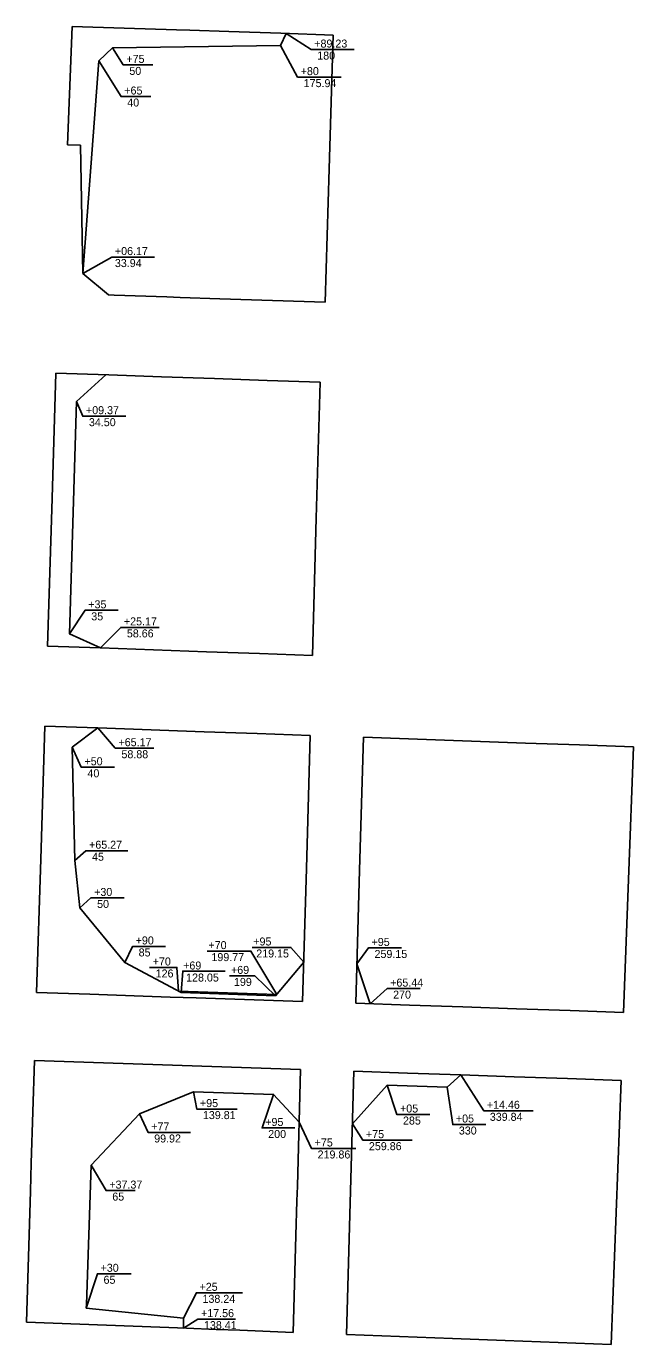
# Model space of a CAD drawing. Extents: x 979729 to 993523, y 1834148 to 1845433.
# Drawn here: x 992510 to 992966, y 1843154 to 1844143 of the extents above; entities that cross this region are included whole.
import ezdxf

# ---------------------------------------------------------------- set-up
doc = ezdxf.new("R2010")
doc.units = 0
for name, color, linetype in [('51', 7, 'Continuous'), ('53', 7, 'Continuous'), ('R_Draft', 7, 'Continuous'), ('S_EXIST_ROW', 7, 'Continuous')]:
    doc.layers.add(name, color=color, linetype=linetype)

msp = doc.modelspace()

# ---------------------------------------------------------------- linework, layer by layer
at = {"layer": '51'}
for p, q in [((992700.72, 1844128.38), (992705.03, 1844137.49)), ((992564.43, 1844117.07), (992574.7, 1844126.79)), ((992574.7, 1844126.79), (992700.72, 1844128.38)), ((992552.28, 1843957.59), (992564.43, 1844117.07)), ((992718.07, 1843441.15), (992697.04, 1843415.86)), ((992635.35, 1843343.93), (992594.87, 1843327.3)), ((992594.87, 1843327.3), (992558.61, 1843288.89)), ((992558.61, 1843288.89), (992555.03, 1843184.46)), ((992555.03, 1843184.46), (992554.93, 1843181.59))]:
    msp.add_line(p, q, dxfattribs=at)
for points in [[(992626.13, 1843418.29), (992583.83, 1843440.75), (992550.22, 1843481.93), (992546.43, 1843517.35), (992544.34, 1843602.2), (992563.73, 1843616.71)], [(992767.88, 1843409.86), (992758.05, 1843439.78)], [(992697.04, 1843415.86), (992626.13, 1843418.29)], [(992835.93, 1843356.52), (992825.77, 1843347.4), (992780.8, 1843348.95), (992754.65, 1843319.82)], [(992714.67, 1843321.2), (992695.51, 1843341.86), (992635.35, 1843343.93)], [(992554.93, 1843181.59), (992627.96, 1843174.08), (992627.87, 1843166.64)]]:
    msp.add_lwpolyline(points, dxfattribs=at)
at = {"layer": '53'}
msp.add_lwpolyline([(992697.85, 1843416.83), (992624.12, 1843419.36)], dxfattribs=at)
at = {"layer": 'R_Draft'}
for p, q in [((992729.64, 1844125.42), (992755.84, 1844125.42)), ((992588.67, 1844113.92), (992604.86, 1844113.92)), ((992719.45, 1844104.76), (992746.14, 1844104.76)), ((992587.11, 1844090.21), (992603.29, 1844090.21)), ((992580.04, 1843969.83), (992606.25, 1843969.83)), ((992558.34, 1843850.51), (992584.54, 1843850.51)), ((992560.08, 1843704.92), (992578.88, 1843704.92)), ((992586.8, 1843692.13), (992609.71, 1843692.13)), ((992582.74, 1843601.52), (992605.64, 1843601.52)), ((992557.23, 1843587.22), (992576.03, 1843587.22)), ((992560.68, 1843524.65), (992586.14, 1843524.65)), ((992564.47, 1843489.23), (992583.27, 1843489.23)), ((992595.64, 1843452.89), (992614.44, 1843452.89)), ((992645.67, 1843449.38), (992672.47, 1843449.38)), ((992679.35, 1843452.1), (992702.42, 1843452.1)), ((992772.6, 1843451.74), (992791.4, 1843451.74)), ((992616.98, 1843437.11), (992602.49, 1843437.11)), ((992633.28, 1843434.37), (992659.12, 1843434.37)), ((992662.38, 1843430.85), (992675.29, 1843430.85)), ((992786.57, 1843421.25), (992805.37, 1843421.25)), ((992643.86, 1843330.91), (992668.05, 1843330.91)), ((992793.95, 1843326.84), (992812.75, 1843326.84)), ((992859.09, 1843329.61), (992890.1, 1843329.61)), ((992692.85, 1843316.75), (992711.33, 1843316.75)), ((992835.85, 1843319.34), (992854.65, 1843319.34)), ((992607.3, 1843313.38), (992633.07, 1843313.38)), ((992768.39, 1843307.61), (992799.46, 1843307.61)), ((992729.91, 1843301.38), (992757.17, 1843301.38)), ((992575.87, 1843269.8), (992591.54, 1843269.8)), ((992569.3, 1843207.41), (992588.76, 1843207.41)), ((992643.53, 1843193.13), (992672.21, 1843193.13)), ((992644.66, 1843173.4), (992666.99, 1843173.4))]:
    msp.add_line(p, q, dxfattribs=at)
for points in [[(992705.03, 1844137.49), (992723.64, 1844125.42), (992729.64, 1844125.42)], [(992574.7, 1844126.79), (992582.67, 1844113.92), (992588.67, 1844113.92)], [(992700.72, 1844128.38), (992713.45, 1844104.76), (992719.45, 1844104.76)], [(992564.43, 1844117.07), (992581.11, 1844090.21), (992587.11, 1844090.21)], [(992552.28, 1843957.59), (992574.04, 1843969.83), (992580.04, 1843969.83)], [(992547.73, 1843861.61), (992552.34, 1843850.51), (992558.34, 1843850.51)], [(992542.25, 1843687.32), (992554.08, 1843704.92), (992560.08, 1843704.92)], [(992565.57, 1843676.69), (992580.8, 1843692.13), (992586.8, 1843692.13)], [(992563.73, 1843616.71), (992576.74, 1843601.52), (992582.74, 1843601.52)], [(992544.34, 1843602.2), (992551.23, 1843587.22), (992557.23, 1843587.22)], [(992546.43, 1843517.35), (992554.68, 1843524.65), (992560.68, 1843524.65)], [(992550.22, 1843481.93), (992558.47, 1843489.23), (992564.47, 1843489.23)], [(992583.83, 1843440.75), (992589.64, 1843452.89), (992595.64, 1843452.89)], [(992697.85, 1843416.83), (992678.47, 1843449.38), (992672.47, 1843449.38)], [(992718.07, 1843441.15), (992708.42, 1843452.1), (992702.42, 1843452.1)], [(992758.05, 1843439.78), (992766.6, 1843451.74), (992772.6, 1843451.74)], [(992624.12, 1843419.36), (992622.98, 1843437.11), (992616.98, 1843437.11)], [(992626.13, 1843418.29), (992627.28, 1843434.37), (992633.28, 1843434.37)], [(992697.04, 1843415.86), (992681.29, 1843430.85), (992675.29, 1843430.85)], [(992767.88, 1843409.86), (992780.57, 1843421.25), (992786.57, 1843421.25)], [(992835.93, 1843356.52), (992853.09, 1843329.61), (992859.09, 1843329.61)], [(992780.8, 1843348.95), (992787.95, 1843326.84), (992793.95, 1843326.84)], [(992825.77, 1843347.4), (992829.85, 1843319.34), (992835.85, 1843319.34)], [(992635.35, 1843343.93), (992637.86, 1843330.91), (992643.86, 1843330.91)], [(992695.51, 1843341.86), (992686.85, 1843316.75), (992692.85, 1843316.75)], [(992594.87, 1843327.3), (992601.3, 1843313.38), (992607.3, 1843313.38)], [(992714.67, 1843321.2), (992723.91, 1843301.38), (992729.91, 1843301.38)], [(992754.65, 1843319.82), (992762.39, 1843307.61), (992768.39, 1843307.61)], [(992558.61, 1843288.89), (992569.87, 1843269.8), (992575.87, 1843269.8)], [(992554.93, 1843181.59), (992563.3, 1843207.41), (992569.3, 1843207.41)], [(992627.96, 1843174.08), (992637.53, 1843193.13), (992643.53, 1843193.13)], [(992627.87, 1843166.64), (992638.66, 1843173.4), (992644.66, 1843173.4)]]:
    msp.add_lwpolyline(points, dxfattribs=at)
at = {"layer": 'S_EXIST_ROW'}
for p, q in [((992540.75, 1844054.04), (992544.3, 1844142.82)), ((992544.3, 1844142.82), (992583.48, 1844141.52)), ((992583.48, 1844141.52), (992622.66, 1844140.22)), ((992622.66, 1844140.22), (992632.65, 1844139.89)), ((992632.65, 1844139.89), (992661.84, 1844138.92)), ((992661.84, 1844138.92), (992701.02, 1844137.62)), ((992701.02, 1844137.62), (992740.19, 1844136.33)), ((992740.19, 1844136.33), (992737.2, 1844036.11)), ((992737.2, 1844036.11), (992734.2, 1843935.9)), ((992575.87, 1843941.3), (992571.74, 1843941.44)), ((992615.45, 1843939.95), (992575.87, 1843941.3)), ((992625.44, 1843939.61), (992615.45, 1843939.95)), ((992655.03, 1843938.6), (992625.44, 1843939.61)), ((992694.6, 1843937.25), (992655.03, 1843938.6)), ((992734.2, 1843935.9), (992694.6, 1843937.25)), ((992532.2, 1843882.76), (992529.01, 1843780.42)), ((992571.84, 1843881.41), (992532.2, 1843882.76)), ((992611.48, 1843880.05), (992571.84, 1843881.41)), ((992651.12, 1843878.7), (992611.48, 1843880.05)), ((992690.76, 1843877.35), (992651.12, 1843878.7)), ((992730.4, 1843875.99), (992690.76, 1843877.35)), ((992727.51, 1843773.99), (992730.4, 1843875.99)), ((992529.01, 1843780.73), (992525.81, 1843678.09)), ((992724.59, 1843671.08), (992727.51, 1843773.99)), ((992525.81, 1843678.09), (992565.57, 1843676.69)), ((992565.57, 1843676.69), (992605.32, 1843675.29)), ((992605.32, 1843675.29), (992645.08, 1843673.89)), ((992645.08, 1843673.89), (992684.83, 1843672.49)), ((992684.83, 1843672.49), (992724.59, 1843671.08)), ((992520.83, 1843518.23), (992523.94, 1843618.12)), ((992523.94, 1843618.12), (992563.73, 1843616.71)), ((992563.73, 1843616.71), (992603.52, 1843615.31)), ((992603.52, 1843615.31), (992623.42, 1843614.61)), ((992643.31, 1843613.91), (992623.42, 1843614.61)), ((992683.1, 1843612.51), (992643.31, 1843613.91)), ((992722.89, 1843611.11), (992683.1, 1843612.51)), ((992720.06, 1843511.34), (992722.89, 1843611.11)), ((992760.04, 1843509.96), (992762.87, 1843609.7)), ((992762.87, 1843609.7), (992803.41, 1843608.27)), ((992803.41, 1843608.27), (992843.96, 1843606.84)), ((992843.96, 1843606.84), (992884.51, 1843605.41)), ((992884.51, 1843605.41), (992925.06, 1843603.99)), ((992925.06, 1843603.99), (992965.6, 1843602.56)), ((992965.6, 1843602.56), (992961.85, 1843502.98)), ((992517.71, 1843418.35), (992520.83, 1843518.23)), ((992717.23, 1843411.58), (992720.06, 1843511.34)), ((992757.21, 1843410.22), (992760.04, 1843509.96)), ((992961.85, 1843502.98), (992958.1, 1843403.41)), ((992557.62, 1843417), (992517.71, 1843418.35)), ((992597.52, 1843415.64), (992557.62, 1843417)), ((992617.86, 1843414.95), (992597.52, 1843415.64)), ((992617.86, 1843414.95), (992637.43, 1843414.29)), ((992637.43, 1843414.29), (992717.23, 1843411.58)), ((992797.39, 1843408.86), (992757.21, 1843410.22)), ((992837.57, 1843407.5), (992797.39, 1843408.86)), ((992877.74, 1843406.13), (992837.57, 1843407.5)), ((992917.92, 1843404.77), (992877.74, 1843406.13)), ((992958.1, 1843403.41), (992917.92, 1843404.77)), ((992516.12, 1843367.38), (992513.72, 1843290.41)), ((992516.12, 1843367.38), (992715.79, 1843360.6)), ((992713.31, 1843273.04), (992715.79, 1843360.6)), ((992755.77, 1843359.24), (992752.97, 1843260.59)), ((992795.85, 1843357.88), (992755.77, 1843359.24)), ((992835.93, 1843356.52), (992795.85, 1843357.88)), ((992876.01, 1843355.16), (992835.93, 1843356.52)), ((992916.09, 1843353.8), (992876.01, 1843355.16)), ((992956.18, 1843352.44), (992916.09, 1843353.8)), ((992952.44, 1843253.36), (992956.18, 1843352.44)), ((992513.06, 1843269.28), (992513.72, 1843290.41)), ((992510, 1843171.18), (992513.06, 1843269.28)), ((992713, 1843262.04), (992713.31, 1843273.04)), ((992712.26, 1843236.01), (992713, 1843262.04)), ((992752.97, 1843260.59), (992750.17, 1843161.93)), ((992948.71, 1843154.28), (992952.44, 1843253.36)), ((992710.2, 1843163.47), (992712.26, 1843236.01)), ((992510, 1843171.18), (992550.04, 1843169.64)), ((992550.04, 1843169.64), (992590.08, 1843168.1)), ((992590.08, 1843168.1), (992630.12, 1843166.55)), ((992630.12, 1843166.55), (992652.37, 1843165.7)), ((992670.16, 1843165.01), (992652.37, 1843165.7)), ((992710.2, 1843163.47), (992670.16, 1843165.01)), ((992750.17, 1843161.93), (992789.88, 1843160.4)), ((992789.88, 1843160.4), (992829.59, 1843158.87)), ((992829.59, 1843158.87), (992849.44, 1843158.11)), ((992849.44, 1843158.11), (992869.29, 1843157.34)), ((992869.29, 1843157.34), (992909, 1843155.81)), ((992909, 1843155.81), (992948.71, 1843154.28))]:
    msp.add_line(p, q, dxfattribs=at)
for points in [[(992571.74, 1843941.44), (992552.28, 1843957.59), (992550.53, 1844053.71), (992540.75, 1844054.04)], [(992547.73, 1843861.61), (992569.7, 1843881.48)], [(992565.57, 1843676.69), (992542.25, 1843687.32), (992547.73, 1843861.61)]]:
    msp.add_lwpolyline(points, dxfattribs=at)

# ---------------------------------------------------------------- texts
at = {"layer": 'R_Draft'}
for s, p in [('+89.23', (992726.01, 1844126.92)), ('+75', (992585.05, 1844115.42)), (' 180', (992726.01, 1844117.92)), (' 50', (992585.05, 1844106.42)), ('+80', (992715.82, 1844106.26)), ('+65', (992583.48, 1844091.71)), (' 175.94', (992715.82, 1844097.26)), (' 40', (992583.48, 1844082.71)), ('33.94', (992576.42, 1843962.33)), ('+06.17', (992576.42, 1843971.33)), ('+09.37', (992554.72, 1843852.01)), (' 34.50', (992554.72, 1843843.01)), ('+35', (992556.46, 1843706.42)), (' 35', (992556.46, 1843697.42)), ('+25.17', (992583.18, 1843693.63)), (' 58.66', (992583.18, 1843684.63)), ('+65.17', (992579.11, 1843603.02)), ('+50', (992553.61, 1843588.72)), (' 58.88', (992579.11, 1843594.02)), (' 40', (992553.61, 1843579.72)), ('+65.27', (992557.06, 1843526.15)), (' 45', (992557.06, 1843517.15)), ('+30', (992560.85, 1843490.73)), (' 50', (992560.85, 1843481.73)), ('+90', (992592.01, 1843454.39)), ('+70', (992646.61, 1843450.88)), ('+95', (992680.25, 1843453.6)), ('+95', (992768.98, 1843453.24)), (' 85', (992592.01, 1843445.39)), ('+70', (992604.78, 1843438.61)), (' 199.77', (992646.61, 1843441.88)), (' 219.15', (992680.25, 1843444.6)), (' 259.15', (992768.98, 1843444.24)), (' 126', (992604.78, 1843429.61)), ('+69', (992627.63, 1843435.58)), ('+69', (992663.53, 1843432.28)), (' 128.05', (992627.63, 1843426.58)), (' 199', (992663.53, 1843423.28)), ('+65.44', (992782.94, 1843422.75)), (' 270', (992782.94, 1843413.75)), ('+95', (992640.23, 1843332.41)), ('+14.46', (992855.46, 1843331.11)), (' 139.81', (992640.23, 1843323.41)), ('+05', (992790.33, 1843328.34)), (' 285', (992790.33, 1843319.34)), ('+05', (992832.23, 1843320.84)), (' 339.84', (992855.46, 1843322.11)), ('+77', (992603.67, 1843314.88)), ('+95', (992689.22, 1843318.25)), (' 330', (992832.23, 1843311.84)), (' 99.92', (992603.67, 1843305.88)), (' 200', (992689.22, 1843309.25)), ('+75', (992726.28, 1843302.88)), ('+75', (992764.77, 1843309.11)), (' 259.86', (992764.77, 1843300.11)), (' 219.86', (992726.28, 1843293.88)), ('+37.37', (992572.24, 1843271.3)), (' 65', (992572.24, 1843262.3)), ('+30', (992565.67, 1843208.91)), (' 65', (992565.67, 1843199.91)), ('+25', (992639.91, 1843194.63)), (' 138.24', (992639.91, 1843185.63)), ('+17.56', (992641.03, 1843174.9)), (' 138.41', (992641.03, 1843165.9))]:
    msp.add_text(s, height=6, rotation=360, dxfattribs=at).set_placement(p)

doc.saveas('drawing.dxf')
